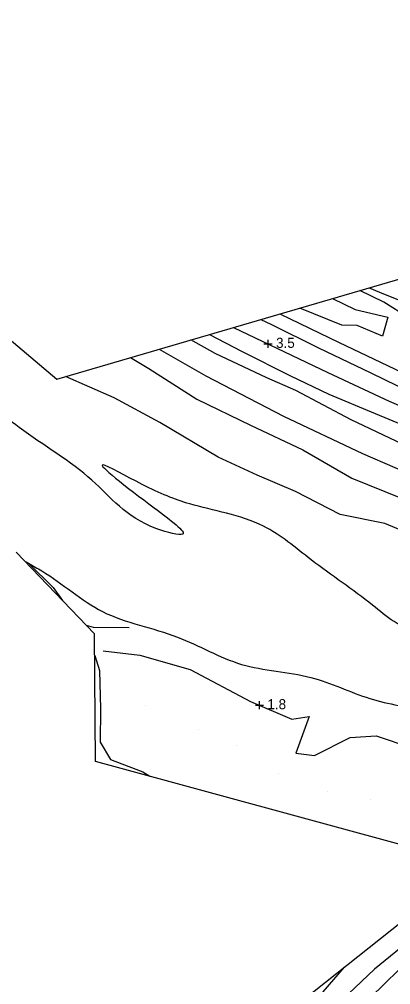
# Model space of a CAD drawing. Extents: x 2316231 to 2323598, y 363169 to 371906.
# Drawn here: x 2321912.2 to 2322096.8, y 368745.7 to 369225.7 of the extents above; entities that cross this region are included whole.
import ezdxf

# ---------------------------------------------------------------- set-up
doc = ezdxf.new("R2010")
doc.units = 0
for name, color, linetype in [('RD_DTM_BkLn1', 7, 'Continuous'), ('RD_DTM_Holes', 7, 'Continuous'), ('RD_DTM_Spot', 7, 'Continuous'), ('RD_DTM_TinHull', 7, 'Continuous'), ('RD_DTM_Void', 7, 'Continuous'), ('RD_EX_H2O', 7, 'Continuous'), ('RD_EX_Road', 7, 'Continuous')]:
    doc.layers.add(name, color=color, linetype=linetype)

msp = doc.modelspace()

# ---------------------------------------------------------------- linework, layer by layer
at = {"layer": 'RD_DTM_BkLn1'}
msp.add_line((2321915.238, 368955.97), (2321915.543, 368955.884), dxfattribs=at)
for points in [[(2322041.686, 369079.242), (2322071.216, 369065.01), (2322095.19, 369053.554), (2322120.342, 369041.704), (2322132.814, 369040.731), (2322129.314, 369045.946), (2322117.771, 369057.122), (2322105.511, 369077.454), (2322093.338, 369085.101), (2322081.506, 369090.886)], [(2322067.835, 369086.889), (2322079.116, 369081.36), (2322095.36, 369077.606), (2322092.79, 369068.17), (2322080.215, 369073.539), (2322072.525, 369073.645), (2322051.613, 369082.145)], [(2322018.729, 369072.529), (2322065.528, 369050.169), (2322096.067, 369035.798), (2322129.009, 369021.597), (2322151.369, 369011.373), (2322182.645, 368999.098), (2322208.994, 368987.56), (2322241.682, 368975.619), (2322268.566, 368965.127), (2322301.837, 368952.965), (2322332.598, 368943.286)], [(2322317.988, 368931.082), (2322290.285, 368942.142), (2322249.993, 368957.091), (2322218.377, 368968.712), (2322181.283, 368984.587), (2322143.628, 368998.031), (2322102.777, 369014.55), (2322077.101, 369026.523), (2322049.645, 369041.2), (2322035.299, 369047.457), (2322009.576, 369059.575), (2321997.518, 369066.327)], [(2321981.677, 369061.694), (2322004.984, 369048.473), (2322043.473, 369028.358), (2322082.824, 369009.751), (2322114.946, 368995.939), (2322145.508, 368984.112), (2322179.113, 368970.562), (2322204.21, 368961.83), (2322237.632, 368950.539), (2322275.392, 368938.24), (2322313.46, 368925.617)], [(2321967.463, 369057.538), (2321976.532, 369052.016), (2322000.508, 369036.905), (2322027.071, 369023.885), (2322053.091, 369011.645), (2322077.506, 368997.498), (2322101.674, 368987.711), (2322120.738, 368978.855), (2322147.723, 368965.019), (2322168.395, 368955.563), (2322194.174, 368947.04), (2322219.087, 368936.411), (2322238.913, 368928.516), (2322269.461, 368920.368), (2322290.164, 368917.026), (2322307.632, 368907.23)], [(2322302.164, 368898.286), (2322288.33, 368904.467), (2322262.059, 368912.743), (2322230.382, 368924.21), (2322199.874, 368934.149), (2322169.428, 368945.677), (2322143.059, 368955.041), (2322113.82, 368966.7), (2322093.855, 368974.991), (2322071.741, 368979.516), (2322049.451, 368990.897), (2322030.511, 368999.047), (2322011.042, 369008.074), (2321981.997, 369025.25), (2321959.297, 369037.435), (2321935.117, 369048.079)], [(2321916.686, 368955.239), (2321929.01, 368943.19), (2321933.679, 368936.733)], [(2321945.404, 368924.502), (2321948.926, 368923.464), (2321966.782, 368923.303)], [(2321953.952, 368911.774), (2321972.122, 368909.542), (2321997.06, 368902.476), (2322027.146, 368886.554), (2322047.704, 368877.755), (2322056.341, 368879.081), (2322049.616, 368860.789), (2322058.942, 368859.678), (2322076.744, 368868.587), (2322089.673, 368869.47), (2322107.26, 368863.417)], [(2321949.712, 368909.381), (2321952.005, 368901.931), (2321952.489, 368882.874), (2321952.449, 368866.241), (2321957.597, 368857.597), (2321973.561, 368851.523), (2321977.096, 368849.345)], [(2321930.605, 368596.571), (2321938.331, 368590.487), (2321945.257, 368588.957), (2321958.627, 368593.051), (2321975.14, 368611.385), (2321985.471, 368626.388), (2321993.622, 368646.301), (2322002.164, 368653.697), (2322016.128, 368667.788), (2322026.984, 368680.568), (2322039.559, 368694.003), (2322056.515, 368709.854), (2322076.146, 368729.087), (2322093.008, 368745.503), (2322110.047, 368762.047), (2322123.963, 368775.868), (2322132.291, 368782.253), (2322144.985, 368783.101), (2322154.541, 368778.756), (2322167.628, 368775.11), (2322181.34, 368772.968), (2322189.256, 368772.495), (2322189.155, 368777.38)], [(2322040.417, 368721.659), (2322047.784, 368728.949), (2322063.229, 368742.085), (2322073.852, 368754.366)]]:
    msp.add_lwpolyline(points, dxfattribs=at)
at = {"layer": 'RD_DTM_Holes'}
for points in [[(2322371.435, 368705.89), (2322322.556, 368765.239), (2322251.156, 368813.888), (2322197.559, 368838.991), (2322160.073, 368853.949), (2322126.291, 368835.422), (2322112.464, 368812.449), (2321950.138, 368856.693), (2321949.626, 368920.098), (2321910.69, 368960.714)], [(2322047.569, 368733.455), (2322152.833, 368817.201), (2322177.852, 368776.527), (2322230.1, 368780.47), (2322278.66, 368734.155)]]:
    msp.add_lwpolyline(points, dxfattribs=at)
at = {"layer": 'RD_DTM_Spot'}
for p, q in [((2321974.784, 368884.482), (2321974.784, 368884.482)), ((2322001.289, 368872.472), (2322001.289, 368872.472)), ((2322019.991, 368864.711), (2322019.991, 368864.711)), ((2322040.987, 368850.476), (2322040.987, 368850.476)), ((2322065.615, 368841.586), (2322065.615, 368841.586)), ((2322086.665, 368837.797), (2322086.665, 368837.797))]:
    msp.add_line(p, q, dxfattribs=at)
at = {"layer": 'RD_DTM_TinHull'}
msp.add_lwpolyline([(2319782.271, 371232.132), (2319735.05, 371773.026), (2320925.274, 371905.831), (2321343.399, 371858.015), (2321109.741, 371125.092), (2321259.088, 370783.878), (2321451.866, 370308.131), (2321545.882, 369878.312), (2321496.483, 369600.925), (2321592.742, 369376.322), (2321772.553, 369180.585), (2321930.831, 369046.826), (2322410.389, 369187.058), (2322700.489, 369322.074), (2323031.423, 369488.086), (2323384.71, 369626.658), (2323598.112, 369182.404), (2323506.079, 369141.824), (2322749.057, 368805.183), (2322437.788, 368637.943)], dxfattribs=at)
at = {"layer": 'RD_DTM_Void'}
for p, q in [((2322035.841, 369062.353), (2322035.841, 369066.353)), ((2322033.841, 369064.353), (2322037.841, 369064.353)), ((2322029.535, 368884.675), (2322033.535, 368884.675)), ((2322031.535, 368882.675), (2322031.535, 368886.675))]:
    msp.add_line(p, q, dxfattribs=at)
at = {"layer": 'RD_EX_H2O'}
for p, q in [((2321915.058, 368956.157), (2321915.543, 368955.884)), ((2321915.543, 368955.884), (2321916.686, 368955.239))]:
    msp.add_line(p, q, dxfattribs=at)
for points in [[(2322086.139, 369092.241), (2322091.246, 369090.052), (2322108.096, 369083.318), (2322111.643, 369072.764), (2322120.552, 369059.569), (2322132.609, 369052.425), (2322153.867, 369041.734), (2322178.906, 369033.182), (2322192.094, 369029.635), (2322203.916, 369029.372), (2322213.584, 369023.444), (2322231.134, 369014.864), (2322250.028, 369003), (2322269.974, 368993.921), (2322287.26, 368989.13), (2322313.393, 368982.718), (2322335.503, 368973.763), (2322349.881, 368965.738), (2322371.778, 368958.42), (2322389.042, 368951.157), (2322396.319, 368948.989), (2322409.539, 368950.147), (2322416.357, 368947.326), (2322425.133, 368940.582)], [(2322125.582, 368786.323), (2322109.12, 368770.036), (2322088.763, 368753.321), (2322069.381, 368734.934), (2322047.442, 368714.669), (2322026.918, 368696.154), (2322022.38, 368691.908)]]:
    msp.add_lwpolyline(points, dxfattribs=at)
for points in [[(2322208.747, 368901.201), (2322183.277, 368905.732), (2322158.063, 368919.923), (2322122.124, 368931.643), (2322122.147, 368923.617), (2322112.165, 368921.307), (2322087.765, 368934.404), (2322057.288, 368956.943), (2322033.541, 368973.676), (2321996.917, 368984.77), (2321973.214, 368994.492), (2321953.822, 369004.127), (2321979.306, 368982.732), (2321993.4, 368969.67), (2321980.55, 368972.438), (2321948.284, 368996.558), (2321912.19, 369022.755), (2321886.426, 369043.496), (2321858.313, 369062.06), (2321841.156, 369069.167), (2321815.393, 369072.996), (2321792.417, 369073.3)], [(2321916.686, 368955.239), (2321923.473, 368951.411), (2321953.602, 368931.228), (2321990.869, 368918.54), (2322022.67, 368904.982), (2322057.091, 368898.483), (2322086.507, 368887.98), (2322115.055, 368881.833), (2322142.054, 368877.395), (2322155.153, 368877.025), (2322177.929, 368870.56), (2322197.809, 368861.983)]]:
    msp.add_spline(points, degree=3, dxfattribs=at)
at = {"layer": 'RD_EX_Road'}
for points in [[(2322032.337, 369076.508), (2322037.321, 369074.192), (2322060.969, 369062.356), (2322086.988, 369050.009), (2322112.838, 369037.354), (2322136.056, 369026.943), (2322159.817, 369017.089), (2322182.288, 369008.501), (2322208.494, 368996.988), (2322235.842, 368986.194), (2322264.049, 368975.391), (2322284.378, 368967.694), (2322315.466, 368957.129), (2322344.928, 368947.689)], [(2322006.713, 369069.015), (2322022.712, 369060.709), (2322047.072, 369048.425), (2322066.039, 369039.415), (2322089.05, 369029.783), (2322111.478, 369020.466), (2322133.703, 369011.116), (2322157.211, 369001.001), (2322182.75, 368989.662), (2322200.364, 368982.897), (2322220.229, 368975.288), (2322241.87, 368967.4), (2322263.306, 368959.382), (2322285.447, 368951.215), (2322314.027, 368940.78), (2322335.964, 368933.82)]]:
    msp.add_lwpolyline(points, dxfattribs=at)

# ---------------------------------------------------------------- texts
at = {"layer": 'RD_DTM_Void'}
for s, p in [('3.5', (2322039.841, 369062.353)), ('1.8', (2322035.535, 368882.675))]:
    msp.add_text(s, height=5, dxfattribs=at).set_placement(p)

doc.saveas('drawing.dxf')
